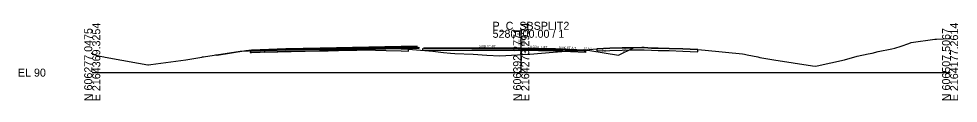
# Model space of a CAD drawing. Extents: x -26 to 1303, y -10 to 12033.
# Drawn here: x -25.7 to 302.8, y 490.3 to 517.8 of the extents above; entities that cross this region are included whole.
import ezdxf

# ---------------------------------------------------------------- set-up
doc = ezdxf.new("R2010")
doc.units = 0
for name, color, linetype in [('RD_GPK_XS_Cell', 7, 'Continuous'), ('RD_XS_Base', 7, 'Continuous'), ('RD_XS_ExGround', 7, 'Continuous'), ('RD_XS_ExPaveRet', 7, 'Continuous'), ('RD_XS_Greenside', 7, 'Continuous'), ('RD_XS_Pave', 7, 'Continuous'), ('RD_XS_PaveOvlay_CP', 7, 'Continuous'), ('RD_XS_TieSlope', 7, 'Continuous'), ('RD_XS_TX_Elev_EX', 7, 'Continuous'), ('RD_XS_TX_Elev_PR', 7, 'Continuous'), ('RD_XS_TX_ShdSlope', 7, 'Continuous'), ('RD_XS_TX_Slope', 7, 'Continuous')]:
    doc.layers.add(name, color=color, linetype=linetype)

msp = doc.modelspace()

# ---------------------------------------------------------------- linework, layer by layer
at = {"layer": 'RD_GPK_XS_Cell'}
for p, q in [((150, 500), (150, 515)), ((0, 500), (150, 500)), ((150, 500), (300, 500))]:
    msp.add_line(p, q, dxfattribs=at)
at = {"layer": 'RD_XS_Base'}
for p, q in [((55.67, 507.53), (55.17, 507.51)), ((55.17, 507.51), (55.17, 507.51)), ((55.17, 507.51), (55.17, 507.01)), ((55.17, 507.01), (55.67, 507.03)), ((67.67, 508.01), (55.67, 507.53)), ((55.67, 507.53), (55.67, 507.53)), ((55.67, 507.03), (67.67, 507.51)), ((55.67, 507.03), (55.67, 507.03)), ((79.67, 508.25), (67.67, 508.01)), ((67.67, 508.01), (67.67, 508.01)), ((67.67, 507.51), (79.67, 507.75)), ((67.67, 507.51), (67.67, 507.51)), ((79.67, 508.25), (113.67, 508.93)), ((114.17, 508.44), (79.67, 507.75)), ((79.67, 507.75), (79.67, 508.41)), ((79.67, 508.41), (79.67, 508.41)), ((79.67, 508.41), (79.67, 508.41)), ((79.67, 508.41), (79.67, 508.25)), ((79.67, 508.25), (79.67, 508.25)), ((79.67, 507.75), (79.67, 508.25)), ((79.67, 508.25), (79.67, 508.25)), ((79.67, 508.25), (79.67, 508.25)), ((79.67, 507.75), (79.67, 507.75)), ((103.67, 508.73), (103.67, 508.73)), ((103.67, 508.73), (103.67, 508.73)), ((103.67, 508.23), (103.67, 508.23)), ((103.67, 508.23), (103.67, 508.23)), ((113.67, 508.93), (113.67, 508.93)), ((114.17, 508.94), (114.17, 508.44)), ((114.17, 508.91), (114.17, 508.91)), ((115.5, 508.4), (115.5, 507.9)), ((115.5, 508.38), (115.5, 508.38)), ((115.5, 507.9), (149.98, 507.72)), ((149.99, 508.22), (116, 508.4)), ((116, 508.4), (116, 508.4)), ((150, 507.72), (150, 508.38)), ((150, 508.38), (150, 508.38)), ((150, 508.38), (150, 508.38)), ((150, 508.38), (150, 508.22)), ((150, 507.72), (150, 508.22)), ((150, 508.22), (150, 508.22)), ((150, 508.22), (150, 508.22)), ((150, 508.22), (150, 508.22)), ((150, 508.22), (162, 507.98)), ((150, 508.22), (150, 508.22)), ((150, 507.72), (150, 507.72)), ((162, 507.48), (150, 507.72)), ((150, 507.72), (150, 507.72)), ((162, 507.98), (162, 507.98)), ((162, 507.98), (172, 507.58)), ((172.5, 507.06), (162, 507.48)), ((162, 507.48), (162, 507.48)), ((172, 507.58), (172, 507.58)), ((172, 507.58), (172.5, 507.56)), ((172.5, 507.56), (172.5, 507.56)), ((172.5, 507.56), (172.5, 507.06))]:
    msp.add_line(p, q, dxfattribs=at)
at = {"layer": 'RD_XS_ExGround'}
msp.add_lwpolyline([(0, 506.5), (2.72, 505.81), (4, 505.49), (4.49, 505.39), (16.14, 503.34), (19.44, 502.77), (19.68, 502.7), (20.54, 502.83), (32.69, 504.5), (38.3, 505.44), (38.5, 505.48), (38.59, 505.5), (38.85, 505.54), (51.73, 507.51), (57.71, 507.78), (60.21, 507.86), (69.6, 508.13), (79.51, 508.42), (82.52, 508.44), (86.11, 508.5), (91.44, 508.58), (91.82, 508.59), (92.49, 508.6), (94.74, 508.79), (95.35, 508.78), (102.74, 508.52), (107.99, 508.37), (110.6, 508.26), (113.42, 508.02), (119.16, 507.5), (122.89, 507.09), (125.3, 506.8), (126.82, 506.75), (133.17, 506.5), (138, 506.15), (142.49, 505.83), (148.77, 506.23), (152.55, 506.5), (153.05, 506.5), (161.2, 507.17), (165.68, 507.5), (169.66, 507.78), (176.49, 508.37), (180.99, 508.54), (185.28, 508.63), (188.43, 508.71), (192.23, 508.77), (192.3, 508.79), (192.98, 508.75), (195.6, 508.62), (197.94, 508.55), (201.71, 508.5), (206.57, 508.28), (209.15, 508.18), (211.8, 508.05), (214.29, 507.87), (227.36, 506.53), (228.13, 506.41), (229.03, 506.25), (232.71, 505.5), (233.5, 505.35), (238.37, 504.51), (251.89, 502.44), (252.85, 502.29), (253.51, 502.42), (263.02, 504.46), (267.51, 505.71), (271.31, 506.56), (272.72, 506.8), (274.84, 507.41), (279.57, 508.32), (280.65, 508.53), (282.88, 509.27), (285.58, 510.19), (286.38, 510.5), (294.66, 511.72), (294.91, 511.76), (295.21, 511.77), (300, 511.97)], dxfattribs=at)
at = {"layer": 'RD_XS_ExPaveRet'}
for points in [[(110.6, 508.26), (107.99, 508.37), (107.99, 508.37), (102.74, 508.52), (102.74, 508.52), (95.35, 508.78), (95.35, 508.78), (94.74, 508.79), (94.74, 508.79), (94.74, 508.79), (92.49, 508.6), (92.49, 508.6), (91.82, 508.59), (91.44, 508.58), (86.11, 508.5), (86.11, 508.5), (86.11, 508.5), (82.52, 508.44), (82.52, 508.44), (79.51, 508.42), (69.6, 508.13), (69.6, 508.13), (60.21, 507.86), (60.21, 507.86), (60.21, 507.86), (60.21, 507.11), (60.21, 507.11), (69.6, 507.38), (69.6, 507.38), (79.51, 507.67), (82.52, 507.69), (82.52, 507.69), (86.11, 507.75), (86.11, 507.75), (86.11, 507.75), (91.44, 507.83), (91.82, 507.84), (92.49, 507.85), (92.49, 507.85), (94.74, 508.04), (94.74, 508.04), (94.74, 508.04), (95.35, 508.03), (95.35, 508.03), (102.74, 507.77), (102.74, 507.77), (107.99, 507.62), (107.99, 507.62), (110.6, 507.51), (110.6, 507.51), (110.6, 508.26), (110.6, 508.26), (110.6, 508.26)], [(110.6, 508.26), (107.99, 508.37), (102.74, 508.52), (95.35, 508.78), (94.74, 508.79), (92.49, 508.6), (91.82, 508.59), (91.44, 508.58), (86.11, 508.5), (82.52, 508.44), (79.51, 508.42), (69.6, 508.13), (60.21, 507.86), (60.21, 507.11), (69.6, 507.38), (79.51, 507.67), (82.52, 507.69), (86.11, 507.75), (91.44, 507.83), (91.82, 507.84), (92.49, 507.85), (94.74, 508.04), (95.35, 508.03), (102.74, 507.77), (107.99, 507.62), (110.6, 507.51), (110.6, 507.51), (110.6, 508.26), (110.6, 508.26)], [(209.15, 508.18), (206.57, 508.28), (206.57, 508.28), (201.71, 508.5), (201.71, 508.5), (197.94, 508.55), (197.94, 508.55), (195.6, 508.62), (195.6, 508.62), (195.6, 508.62), (192.98, 508.75), (192.3, 508.79), (192.3, 508.79), (192.23, 508.77), (192.23, 508.77), (188.43, 508.71), (188.43, 508.71), (188.43, 508.71), (185.28, 508.63), (185.28, 508.63), (180.99, 508.54), (180.99, 508.54), (176.49, 508.37), (176.49, 508.37), (176.49, 507.62), (180.99, 507.79), (180.99, 507.79), (185.28, 507.88), (185.28, 507.88), (188.43, 507.96), (188.43, 507.96), (188.43, 507.96), (192.23, 508.02), (192.23, 508.02), (192.3, 508.04), (192.3, 508.04), (192.98, 508), (195.6, 507.87), (195.6, 507.87), (195.6, 507.87), (197.94, 507.8), (197.94, 507.8), (201.71, 507.75), (201.71, 507.75), (206.57, 507.53), (206.57, 507.53), (209.15, 507.43), (209.15, 507.43), (211.8, 507.3), (211.8, 508.05), (211.8, 508.05), (209.15, 508.18), (209.15, 508.18)], [(209.15, 508.18), (206.57, 508.28), (201.71, 508.5), (197.94, 508.55), (195.6, 508.62), (192.98, 508.75), (192.3, 508.79), (192.23, 508.77), (188.43, 508.71), (185.28, 508.63), (180.99, 508.54), (176.49, 508.37), (176.49, 507.62), (180.99, 507.79), (185.28, 507.88), (188.43, 507.96), (192.23, 508.02), (192.3, 508.04), (192.98, 508), (195.6, 507.87), (197.94, 507.8), (201.71, 507.75), (206.57, 507.53), (209.15, 507.43), (211.8, 507.3), (211.8, 508.05), (209.15, 508.18)]]:
    msp.add_lwpolyline(points, dxfattribs=at)
at = {"layer": 'RD_XS_Greenside'}
for p, q in [((43.67, 506.02), (43.27, 506.22)), ((53.67, 507.68), (43.67, 506.02)), ((174, 507.73), (184, 506.07)), ((184, 506.07), (189.32, 508.73))]:
    msp.add_line(p, q, dxfattribs=at)
at = {"layer": 'RD_XS_Pave'}
for p, q in [((113.67, 509.24), (79.67, 508.56)), ((113.67, 509.09), (113.67, 509.24)), ((113.67, 509.24), (113.67, 509.24)), ((67.67, 508.32), (55.67, 507.84)), ((55.67, 507.69), (67.67, 508.17)), ((67.67, 508.17), (55.67, 507.69)), ((55.67, 507.53), (67.67, 508.01)), ((55.67, 507.84), (55.67, 507.84)), ((55.67, 507.84), (55.67, 507.69)), ((55.67, 507.69), (55.67, 507.69)), ((55.67, 507.69), (55.67, 507.53)), ((79.67, 508.56), (67.67, 508.32)), ((67.67, 508.17), (79.67, 508.41)), ((79.67, 508.41), (67.67, 508.17)), ((67.67, 508.32), (67.67, 508.32)), ((67.67, 508.01), (79.67, 508.25)), ((67.67, 508.17), (67.67, 508.17)), ((67.67, 508.17), (67.67, 508.17)), ((67.67, 508.01), (67.67, 508.01)), ((113.67, 509.09), (79.67, 508.41)), ((79.67, 508.41), (113.67, 509.09)), ((79.67, 508.25), (114.17, 508.94)), ((79.67, 508.56), (79.67, 508.56)), ((79.67, 508.25), (79.67, 508.41)), ((79.67, 508.41), (79.67, 508.41)), ((79.67, 508.41), (79.67, 508.41)), ((79.67, 508.41), (79.67, 508.41)), ((79.67, 508.41), (79.67, 508.41)), ((79.67, 508.41), (79.67, 508.25)), ((79.67, 508.41), (79.67, 508.41)), ((79.67, 508.25), (79.67, 508.25)), ((79.67, 508.25), (79.67, 508.25)), ((103.67, 509.04), (103.67, 509.04)), ((103.67, 509.04), (103.67, 509.04)), ((103.67, 508.89), (103.67, 508.89)), ((103.67, 508.89), (103.67, 508.89)), ((103.67, 508.89), (103.67, 508.89)), ((103.67, 508.89), (103.67, 508.89)), ((103.67, 508.73), (103.67, 508.73)), ((103.67, 508.73), (103.67, 508.73)), ((113.67, 508.93), (113.67, 509.09)), ((113.67, 509.09), (113.67, 509.09)), ((115.5, 508.4), (149.99, 508.22)), ((116, 508.71), (116, 508.71)), ((116, 508.71), (116, 508.56)), ((150, 508.53), (116, 508.71)), ((116, 508.56), (116, 508.56)), ((116, 508.56), (116, 508.4)), ((150, 508.38), (116, 508.56)), ((116, 508.56), (150, 508.38)), ((162, 508.29), (150, 508.53)), ((150, 508.53), (150, 508.53)), ((150, 508.53), (150, 508.53)), ((150, 508.22), (150, 508.38)), ((150, 508.38), (150, 508.38)), ((150, 508.38), (150, 508.38)), ((150, 508.38), (150, 508.38)), ((150, 508.38), (150, 508.38)), ((150, 508.38), (162, 508.14)), ((162, 508.14), (150, 508.38)), ((150, 508.38), (150, 508.38)), ((150, 508.38), (150, 508.38)), ((150, 508.38), (150, 508.38)), ((150, 508.38), (150, 508.22)), ((150, 508.22), (150, 508.22)), ((150, 508.22), (150, 508.22)), ((150, 508.22), (150, 508.22)), ((150, 508.22), (162, 507.98)), ((172, 507.89), (162, 508.29)), ((162, 508.29), (162, 508.29)), ((162, 508.14), (162, 508.14)), ((162, 508.14), (172, 507.74)), ((172, 507.74), (162, 508.14)), ((162, 508.14), (162, 508.14)), ((162, 507.98), (172, 507.58)), ((162, 507.98), (162, 507.98)), ((172, 507.74), (172, 507.89)), ((172, 507.89), (172, 507.89)), ((172, 507.58), (172, 507.74)), ((172, 507.74), (172, 507.74))]:
    msp.add_line(p, q, dxfattribs=at)
at = {"layer": 'RD_XS_PaveOvlay_CP'}
for p, q in [((113.67, 509.24), (79.67, 508.56)), ((67.67, 508.32), (55.67, 507.84)), ((79.67, 508.56), (67.67, 508.32)), ((67.67, 508.32), (67.67, 508.32)), ((79.67, 508.56), (79.67, 508.56)), ((103.67, 509.04), (103.67, 509.04)), ((103.67, 509.04), (103.67, 509.04)), ((150, 508.53), (116, 508.71)), ((162, 508.29), (150, 508.53)), ((150, 508.53), (150, 508.53)), ((150, 508.53), (150, 508.53)), ((172, 507.89), (162, 508.29)), ((162, 508.29), (162, 508.29))]:
    msp.add_line(p, q, dxfattribs=at)
at = {"layer": 'RD_XS_TieSlope'}
for p, q in [((55.67, 507.84), (53.67, 507.68)), ((172, 507.89), (174, 507.73))]:
    msp.add_line(p, q, dxfattribs=at)

# ---------------------------------------------------------------- texts
at = {"layer": 'RD_GPK_XS_Cell'}
for s, p in [('E 2164369.3254', (2.8, 490)), ('E 2164273.2934', (152.8, 490)), ('E 2164177.2614', (302.8, 490)), ('N 606277.0475', (0, 490)), ('N 606392.2771', (150, 490)), ('N 606507.5067', (300, 490))]:
    msp.add_text(s, height=2.8, rotation=90, dxfattribs=at).set_placement(p)
for s, p in [('P_C_SBSPLIT2', (140, 515)), ('5280+00.00 / 1', (140, 512.2)), ('EL 90', (-26, 498.6))]:
    msp.add_text(s, height=2.8, dxfattribs=at).set_placement(p)
at = {"layer": 'RD_XS_TX_Elev_EX'}
msp.add_text('96.32', height=0.6, rotation=90, dxfattribs=at).set_placement((149.66, 509.52))
at = {"layer": 'RD_XS_TX_Elev_PR'}
msp.add_text('98.53', height=1, rotation=90, dxfattribs=at).set_placement((151.33, 509.21))
at = {"layer": 'RD_XS_TX_ShdSlope'}
msp.add_text('12.5:1', height=0.75, rotation=355.4261, dxfattribs=at).set_placement((171.8, 508.18))
at = {"layer": 'RD_XS_TX_Slope'}
for s, rotation, p in [('0.005 FT./FT.', 359.6963, (135.16, 508.83)), ('0.020 FT./FT.', 358.8542, (153.16, 508.69)), ('0.040 FT./FT.', 357.7094, (163.17, 508.46)), ('6:1', 350.5358, (178.13, 507.44)), ('2:1', 26.5651, (185.62, 507.31))]:
    msp.add_text(s, height=0.75, rotation=rotation, dxfattribs=at).set_placement(p)

doc.saveas('drawing.dxf')
